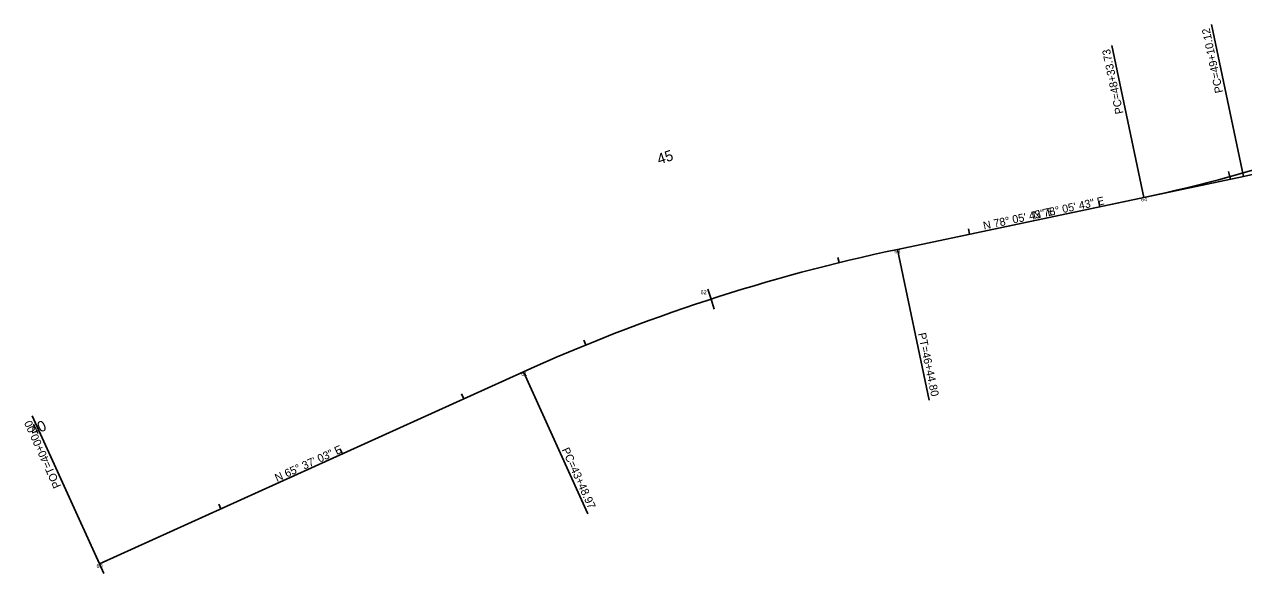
# Model space of a CAD drawing. Extents: x 1965771 to 1970246, y 1117124 to 1118239.
# Drawn here: x 1965771 to 1966685, y 1117124 to 1117536 of the extents above; entities that cross this region are included whole.
import ezdxf

# ---------------------------------------------------------------- set-up
doc = ezdxf.new("R2010")
doc.units = 0
for name, color, linetype in [('RD_HC_Cl', 7, 'Continuous'), ('RD_HC_Data', 7, 'Continuous'), ('RD_HC_Data_Tic', 7, 'Continuous'), ('RD_HC_Points', 7, 'Continuous'), ('RD_HC_TX_Sta50', 7, 'Continuous')]:
    doc.layers.add(name, color=color, linetype=linetype)

msp = doc.modelspace()

# ---------------------------------------------------------------- linework, layer by layer
at = {"layer": 'RD_HC_Cl'}
for p, q in [((1966425.26, 1117367.21), (1966684.87, 1117421.95)), ((1966425.26, 1117367.21), (1966610.12, 1117406.19)), ((1965826.85, 1117131.21), (1966144.7, 1117275.28)), ((1965826.85, 1117131.21), (1966144.7, 1117275.28))]:
    msp.add_line(p, q, dxfattribs=at)
for centre, radius, start, end in [((1966373.74, 1118527.46), 1145.91, 281.90472, 295.04633), ((1966579.59, 1117921.32), 510.35, 281.90472, 291.99584), ((1966705.48, 1116038.04), 1358.39, 101.90472, 114.38256), ((1966705.48, 1116038.04), 1358.39, 101.90472, 114.38256)]:
    msp.add_arc(centre, radius, start, end, dxfattribs=at)
at = {"layer": 'RD_HC_Data'}
for p, q in [((1966684.87, 1117421.95), (1966660.83, 1117536.01)), ((1966610.12, 1117406.19), (1966586.1, 1117520.13)), ((1966425.26, 1117367.21), (1966449.13, 1117253.99)), ((1966425.26, 1117367.21), (1966449.13, 1117253.99)), ((1966144.7, 1117275.28), (1966192.97, 1117168.77)), ((1966144.7, 1117275.28), (1966192.97, 1117168.77)), ((1965826.85, 1117131.21), (1965776.45, 1117242.4)), ((1965826.85, 1117131.21), (1965776.45, 1117242.4))]:
    msp.add_line(p, q, dxfattribs=at)
at = {"layer": 'RD_HC_Data_Tic'}
for p, q in [((1966674.54, 1117421.73), (1966673.49, 1117425.59)), ((1966674.97, 1117419.86), (1966674.15, 1117423.77)), ((1966577.12, 1117399.23), (1966576.3, 1117403.14)), ((1966577.12, 1117399.23), (1966576.3, 1117403.14)), ((1966479.28, 1117378.6), (1966478.45, 1117382.52)), ((1966479.28, 1117378.6), (1966478.45, 1117382.52)), ((1966381.59, 1117357.25), (1966380.63, 1117361.14)), ((1966381.59, 1117357.25), (1966380.63, 1117361.14)), ((1966285.44, 1117329.86), (1966282.96, 1117337.46)), ((1966285.44, 1117329.86), (1966282.96, 1117337.46)), ((1966285.44, 1117329.86), (1966287.91, 1117322.25)), ((1966285.44, 1117329.86), (1966287.91, 1117322.25)), ((1966191.56, 1117295.46), (1966190.05, 1117299.17)), ((1966191.56, 1117295.46), (1966190.05, 1117299.17)), ((1966100.09, 1117255.06), (1966098.44, 1117258.7)), ((1966100.09, 1117255.06), (1966098.44, 1117258.7)), ((1966009.01, 1117213.78), (1966007.36, 1117217.42)), ((1966009.01, 1117213.78), (1966007.36, 1117217.42)), ((1965917.93, 1117172.49), (1965916.28, 1117176.14)), ((1965917.93, 1117172.49), (1965916.28, 1117176.14)), ((1965826.85, 1117131.21), (1965823.55, 1117138.5)), ((1965826.85, 1117131.21), (1965823.55, 1117138.5)), ((1965826.85, 1117131.21), (1965830.15, 1117123.92)), ((1965826.85, 1117131.21), (1965830.15, 1117123.92))]:
    msp.add_line(p, q, dxfattribs=at)

# ---------------------------------------------------------------- texts
at = {"layer": 'RD_HC_Data'}
for s, rotation, p in [('PC=49+10.12', 101.90472, (1966669.51, 1117485.13)), ('PC=48+33.73', 101.90472, (1966594.76, 1117469.38)), ('N 78%%d 05\' 43" E', 11.90472, (1966527.58, 1117389.81)), ('N 78%%d 05\' 43" E', 11.90472, (1966490.2, 1117381.93)), ('PT=46+44.80', 281.90472, (1966440.63, 1117304.03)), ('PT=46+44.80', 281.90472, (1966440.63, 1117304.03)), ('POT=40+00.00', 114.38256, (1965798.2, 1117189.59)), ('POT=40+00.00', 114.38256, (1965798.2, 1117189.59)), ('N 65%%d 37\' 03" E', 24.38256, (1965959.97, 1117192.64)), ('N 65%%d 37\' 03" E', 24.38256, (1965959.97, 1117192.64)), ('PC=43+48.97', 294.38256, (1966173.35, 1117216.9)), ('PC=43+48.97', 294.38256, (1966173.35, 1117216.9))]:
    msp.add_text(s, height=6, rotation=rotation, dxfattribs=at).set_placement(p)
at = {"layer": 'RD_HC_Points'}
for s, p in [('64', (1966607.92, 1117403.19)), ('63', (1966422.89, 1117364.21)), ('62', (1966277.6, 1117333.58)), ('61', (1966143.1, 1117272.28)), ('60', (1965824.6, 1117128.21))]:
    msp.add_text(s, height=3, dxfattribs=at).set_placement(p)
at = {"layer": 'RD_HC_TX_Sta50'}
for s, rotation, p in [('45', 18.01224, (1966246.56, 1117430.78)), ('45', 18.01224, (1966246.56, 1117430.78)), ('40', 24.38256, (1965776.99, 1117227.19)), ('40', 24.38256, (1965776.99, 1117227.19))]:
    msp.add_text(s, height=8, rotation=rotation, dxfattribs=at).set_placement(p)

doc.saveas('drawing.dxf')
